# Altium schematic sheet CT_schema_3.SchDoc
size 368 x 207 mm
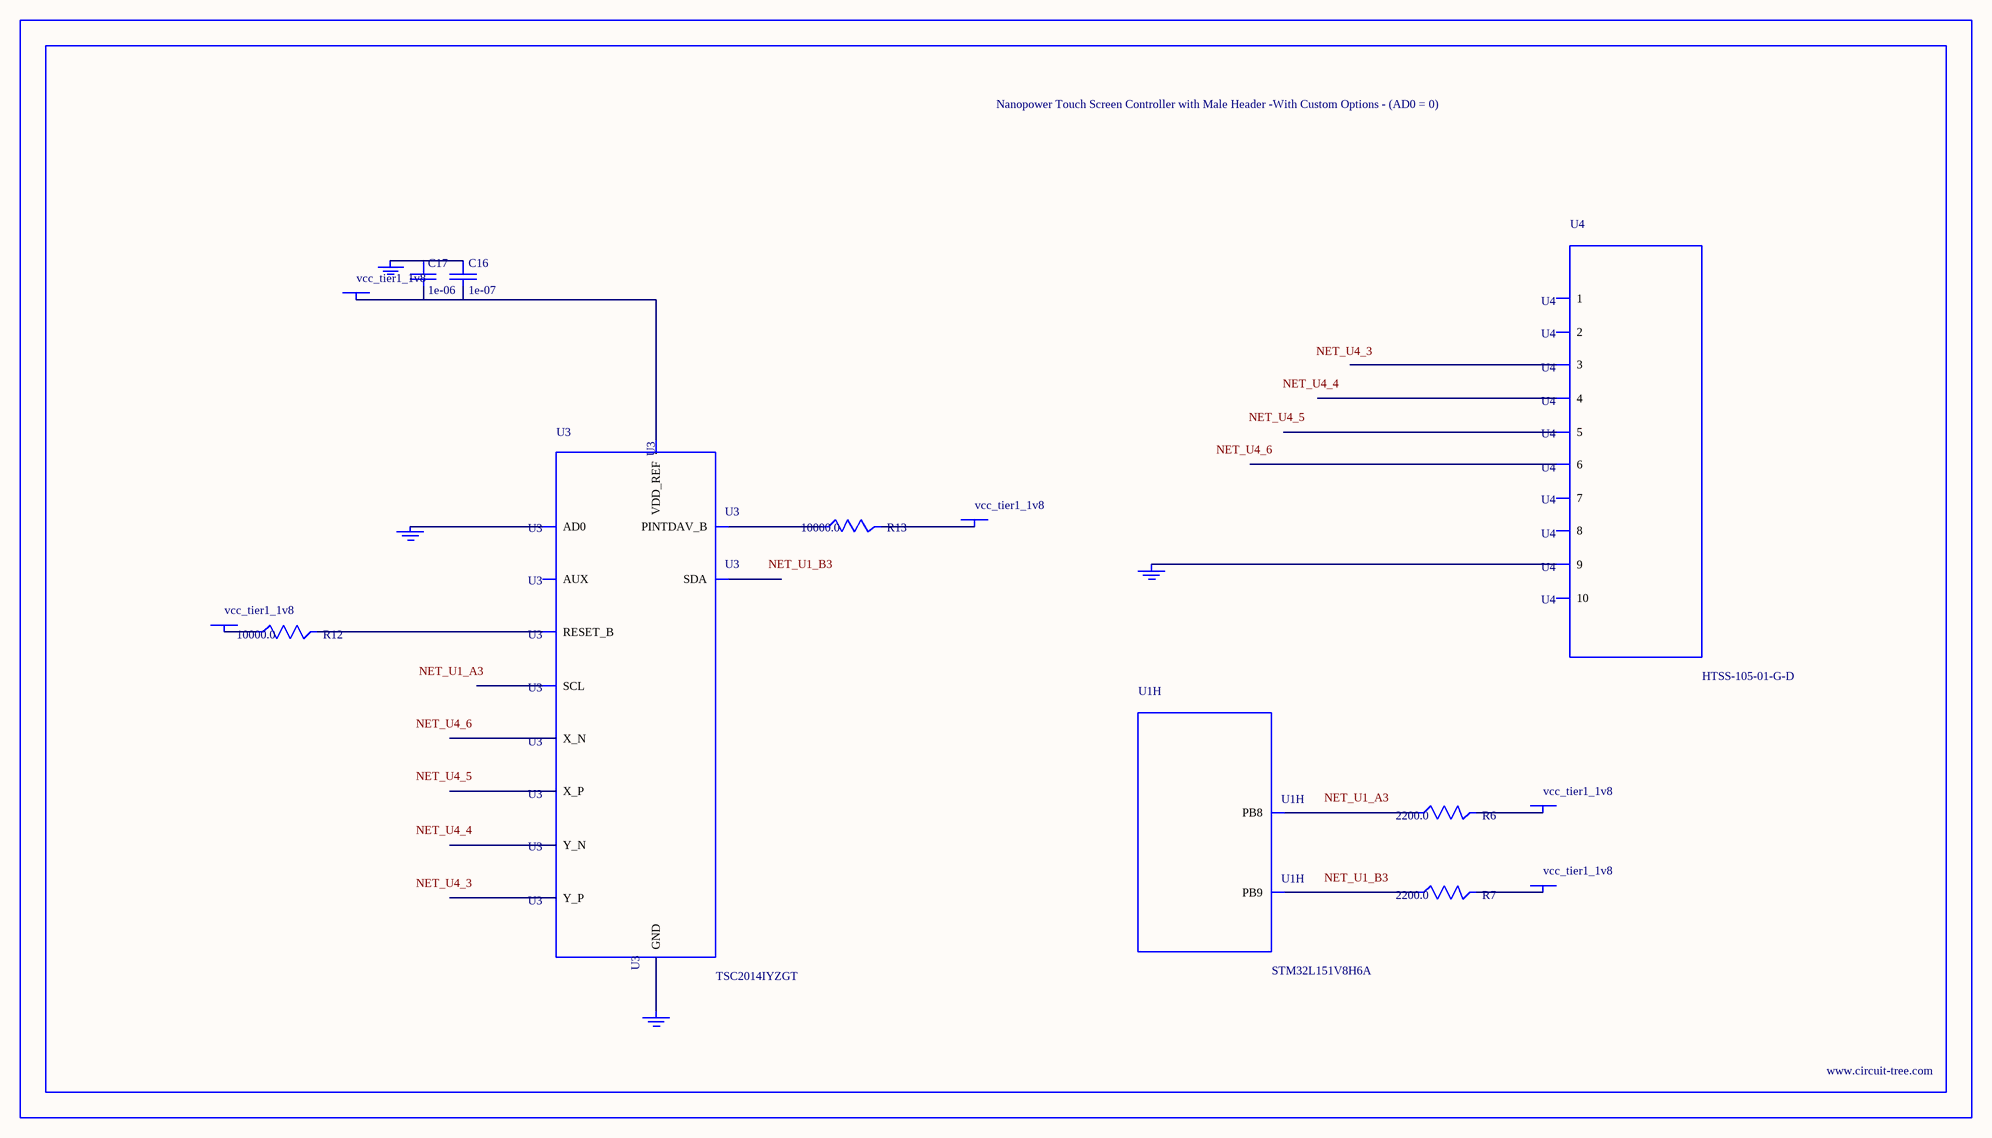
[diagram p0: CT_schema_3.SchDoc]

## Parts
BORDER2  (no value)
C16  1e-07  [C0402]
C17  1e-06  [C0603]
GND_INSTANCE_2_0  (no value)
GND_INSTANCE_2_1  (no value)
GND_INSTANCE_2_2  (no value)
GND_INSTANCE_2_3  (no value)
POWER_INSTANCE_2_0  vcc_tier1_1v8
POWER_INSTANCE_2_1  vcc_tier1_1v8
POWER_INSTANCE_2_2  vcc_tier1_1v8
POWER_INSTANCE_2_3  vcc_tier1_1v8
POWER_INSTANCE_2_4  vcc_tier1_1v8
R6  2200.0  [R0603]
R7  2200.0  [R0603]
R12  10000.0  [R0603]
R13  10000.0  [R0603]
U1  STM32L151V8H6A  [UFBGA100]  (part H of 9)
U3  TSC2014IYZGT  [TSC2014IYZGT]
U4  HTSS-105-01-G-D  [HTSS-105-01-G-D]

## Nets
NetC16_1: C16.1 C17.1 GND_INSTANCE_2_0.0(GND)
NetC16_2: C16.2 C17.2 POWER_INSTANCE_2_2.0(PWR) U3.A2(VDD_REF)
NetGND_INSTANCE_2_1_0: GND_INSTANCE_2_1.0(GND) U3.B2(AD0)
NetGND_INSTANCE_2_2_0: GND_INSTANCE_2_2.0(GND) U3.D2(GND)
NetGND_INSTANCE_2_3_0: GND_INSTANCE_2_3.0(GND) U4.9
NetPOWER_INSTANCE_2_0_0: POWER_INSTANCE_2_0.0(PWR) R12.1
NetPOWER_INSTANCE_2_1_0: POWER_INSTANCE_2_1.0(PWR) R13.2
NetPOWER_INSTANCE_2_3_0: POWER_INSTANCE_2_3.0(PWR) R6.2
NetPOWER_INSTANCE_2_4_0: POWER_INSTANCE_2_4.0(PWR) R7.2
NetR6_1: R6.1 U1.A3(PB8)
NetR7_1: R7.1 U1.B3(PB9)
NetR12_2: R12.2 U3.C2(RESET_B)
NetR13_1: R13.1 U3.B1(PINTDAV_B)

Not connected (* = marked no-connect by the designer): U3 A1(AUX) A3(X_P) B3(Y_P) C1(SDA) C3(X_N) D1(SCL) D3(Y_N); U4 1 2 3 4 5 6 7 8 10

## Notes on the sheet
- Labels drawn without touching a wire or pin: NET_U1_A3, NET_U1_B3, NET_U4_3, NET_U4_4, NET_U4_5, NET_U4_6

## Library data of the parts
BORDER2 = BORDER_PAGE2
C16 = C0402C104K3RACTU
C17 = C0603C105K3RACTU
GND_INSTANCE_2_0-GND_INSTANCE_2_3 = GND
POWER_INSTANCE_2_0-POWER_INSTANCE_2_4 = PWR
R6 R7 = RC0603JR-072K2L
R12 R13 = RC0603JR-0710KL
